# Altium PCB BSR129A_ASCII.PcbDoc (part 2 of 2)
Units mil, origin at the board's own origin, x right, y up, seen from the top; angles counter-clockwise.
Board outline 2165.87 x 2165.5 mil, 2 copper layers (Top Layer, Bottom Layer), stack 61.2 mil thick; 64 components, 16 nets, 93 pads, 184 vias.
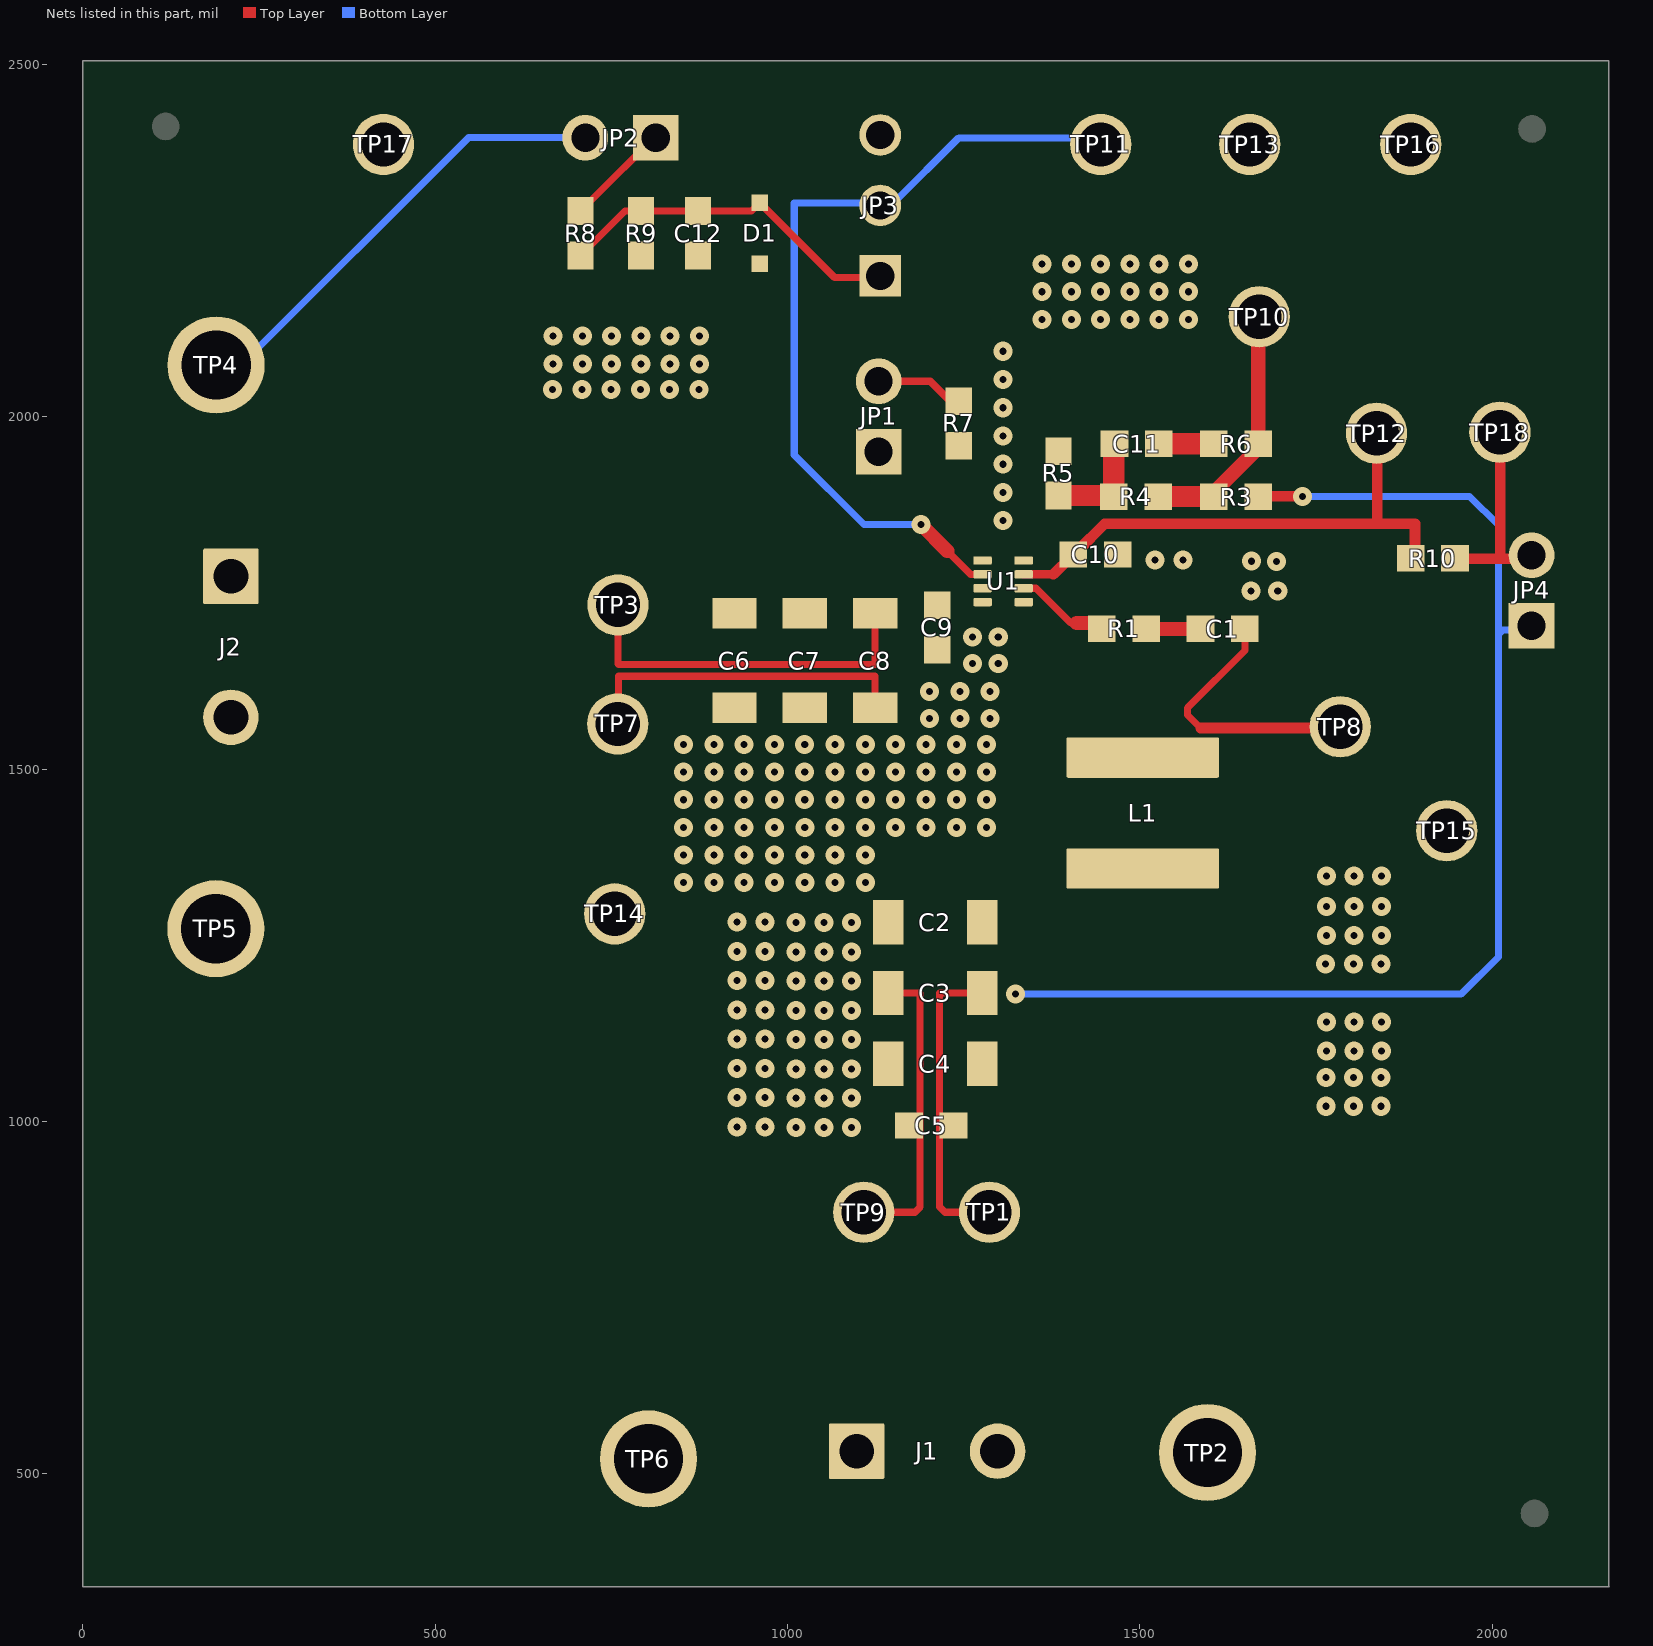
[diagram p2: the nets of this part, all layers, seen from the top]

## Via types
v1: diameter 27, hole 10, Top Layer to Bottom Layer, 184 vias

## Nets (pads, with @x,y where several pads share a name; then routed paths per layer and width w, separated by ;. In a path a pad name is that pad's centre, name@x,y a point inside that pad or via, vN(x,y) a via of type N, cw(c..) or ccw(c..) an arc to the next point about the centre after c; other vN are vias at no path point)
BST: R1.1 U1.6 | length 131.4
  Top Layer w10: U1.6@1335,1756.69 1352.81,1756.69 1402,1707.5 1410.5,1707.5
  Top Layer w20: 1410.5,1707.5 R1.1@1446,1707.5
EN: JP3.2 TP11.1 U1.2 | length 1173.2
  Top Layer w10: 1226.66,1809.66 1259.96,1776.37 U1.2@1276.73,1776.37
  Top Layer w20: v1(1189.33,1847) 1226.66,1809.66
  Bottom Layer w10: v1(1189.33,1847) 1108.3,1847 1009.5,1945.8 1009.5,2303.5 1131.5,2303.5 1132.5,2302.5 1149.5,2302.5 1243,2396 1435,2396 TP11.1@1444.5,2386.5
FB: C11.2 R4.1 R5.2 U1.8 | length 154.5
  Top Layer w30: R5.2@1384.48,1888.23 1461.49,1888.23 R4.1@1462.99,1886.73 1462.99,1960.74 C11.2@1463.98,1961.73
GND: C2.2 C3.2 C4.2 C5.2 C6.2 C7.2 C8.2 C9.2 C10.2 C12.2 D1.2 J1.1 J2.2 JP3.3 R5.1 R7.1 R9.1 TP5.1 TP6.1 TP7.1 TP9.1 TP13.1 TP14.1 TP15.1 TP16.1 TP17.1 U1.4 | length 964.9
  Top Layer w10: TP7.1@760,1529 760,1631.75 1124,1631.75 C8.2@1124,1587.54 ; C7.2@1024.5,1587.04 C7.2@1025,1587.54 ; TP9.1@1108,871 1180.88,871 1188.25,878.37 1188.25,1182.25 C3.2@1142.57,1182.25 ; C5.2@1169.69,991.35 C5.2@1172.5,994.16 C5.2@1187.91,994.16
  Bottom Layer w10: v1@1024.01,1535.35 v1(1024.36,1535) ; v1@1024.06,1417.6 v1(1024.41,1417.25)
  other v1: 1012,991.35 1051.5,991.35 1091,991.35 928.5,992.15 968,992.15 1764,1021.48 1803.25,1021.48 1842.5,1021.48 1012,1032.88 1051.5,1032.88 1091,1032.88 928.5,1033.69 968,1033.69 1764,1062.5 1803.25,1062.5 1842.5,1062.5 1012,1074.42 1051.5,1074.42 1091,1074.42 928.5,1075.23 968,1075.23 1764.75,1099.93 1804,1099.93 1843.25,1099.93 1012,1115.96 1051.5,1115.96 1091,1115.96 928.5,1116.77 968,1116.77 1764.75,1140.95 1804,1140.95 1843.25,1140.95 928.5,1158.31 968,1158.31 1012,1157.5 1051.5,1157.5 1091,1157.5 1012,1199.04 1051.5,1199.04 1091,1199.04 928.5,1199.85 968,1199.85 1763.75,1223.55 1803,1223.55 1842.25,1223.55 928.5,1241.39 968,1241.39 1012,1240.58 1051.5,1240.58 1091,1240.58 1764.75,1264.02 1804,1264.02 1843.25,1264.02 1012,1282.12 1051.5,1282.12 1091,1282.12 928.5,1282.93 968,1282.93 1764.75,1305.05 1804,1305.05 1843.25,1305.05 852.32,1338.75 895.34,1338.75 938.36,1338.75 981.39,1338.75 1024.41,1338.75 1067.43,1338.75 1110.45,1338.75 1764.75,1348.55 1804,1348.55 1843.25,1348.55 852.32,1378 895.34,1378 938.36,1378 981.39,1378 1024.41,1378 1067.43,1378 1110.45,1378 852.32,1417.25 895.34,1417.25 938.36,1417.25 981.39,1417.25 1067.43,1417.25 1110.45,1417.25 1153.48,1417.25 1196.5,1417.25 1239.52,1417.25 1282.55,1417.25 852.27,1456.5 895.3,1456.5 938.32,1456.5 981.34,1456.5 1024.36,1456.5 1067.39,1456.5 1110.41,1456.5 1153.43,1456.5 1196.45,1456.5 1239.48,1456.5 1282.5,1456.5 852.27,1495.75 895.3,1495.75 938.32,1495.75 981.34,1495.75 1024.36,1495.75 1067.39,1495.75 1110.41,1495.75 1153.43,1495.75 1196.45,1495.75 1239.48,1495.75 1282.5,1495.75 852.27,1535 895.3,1535 938.32,1535 981.34,1535 1067.39,1535 1110.41,1535 1153.43,1535 1196.45,1535 1239.48,1535 1282.5,1535 1201.45,1572 1244.48,1572 1287.5,1572 1201.45,1610.25 1244.48,1610.25 1287.5,1610.25 1262.48,1650 1299.02,1650 1262.48,1687.25 1299.02,1687.5 1695.72,1752.5 1657.5,1752.73 1694,1794.5 1658.5,1795 1561,1796.5 1521.48,1796.77 1305.5,1852.5 1305.5,1892.59 1305.5,1932.67 1305.5,1972.76 1305.5,2012.85 666.46,2039 708,2039 749.54,2039 791.08,2039 832.62,2039 874.15,2039 1305.5,2052.94 667.31,2074.95 708.85,2074.95 750.38,2074.95 791.92,2074.95 833.46,2074.95 875,2074.95 1305.5,2093.02 667.31,2114.45 708.85,2114.45 750.38,2114.45 791.92,2114.45 833.46,2114.45 875,2114.45 1361.31,2138 1402.85,2138 1444.38,2138 1485.92,2138 1527.46,2138 1569,2138 1361.31,2177.5 1402.85,2177.5 1444.38,2177.5 1485.92,2177.5 1527.46,2177.5 1569,2177.5 1361.31,2217 1402.85,2217 1444.38,2217 1485.92,2217 1527.46,2217 1569,2217
NetC1_2: C1.2 R1.2 | length 77
  Top Layer w20: R1.2@1508.99,1699 C1.2@1586,1699
NetC11_1: C11.1 R6.1 | length 78
  Top Layer w30: C11.1@1526.97,1961.73 R6.1@1604.99,1961.73
NetC12_1: C12.1 D1.1 JP3.1 R8.1 R9.2 | length 486.2
  Top Layer w10: R8.1@706.17,2228.95 769.16,2291.94 R9.2@792,2291.94 C12.1@872.9,2291.94 948.63,2291.94 D1.1@960.5,2303.81 1066.31,2198 JP3.1@1117.5,2198
NetJP1_2: JP1.2 R7.2 | length 135.2
  Top Layer w10: JP1.2@1120,2073.5 1143.02,2050.48 1202.51,2050.48 R7.2@1233,2019.99
NetJP2_1: JP2.1 R8.2 | length 172.3
  Top Layer w10: R8.2@706.17,2291.94 JP2.1@828,2413.77
NetJP4_2: JP4.2 R10.1 TP18.1 | length 254.2
  Top Layer w15: R10.1@1962.5,1798.5 2011.5,1798.5 ; TP18.1@2011.5,1955.98 2011.5,1798.5 ; JP4.2@2058,1801.5 2055,1798.5 2011.5,1798.5
NetR3_1: R3.1 R4.2 R6.2 TP10.1 | length 337.1
  Top Layer w10: R3.1@1604.98,1886.73 R3.1@1604.98,1892.98 ; R6.2@1667.98,1955.98 R6.2@1667.98,1961.73
  Top Layer w20: R3.1@1604.98,1892.98 R6.2@1667.98,1955.98 ; R6.2@1667.98,1961.73 1667.98,2117.98 TP10.1@1668.5,2118.5
  Top Layer w30: R4.2@1525.98,1886.73 R3.1@1604.98,1886.73
RT: JP1.1 U1.1
SS: C10.1 R10.2 TP12.1 U1.7 | length 738.8
  Top Layer w10: C10.1@1411.5,1801.13 C10.1@1412.13,1801.13 ; 1836,1848 1837,1849
  Top Layer w12: U1.7@1335,1776.37 1377.37,1776.37
  Top Layer w15: 1377.37,1776.37 C10.1@1402.5,1801.5 ; C10.1@1411.51,1809.5 1450.01,1848 1836,1848 1890.5,1848 1890.5,1807.51 R10.2@1893.39,1804.62 ; 1837,1849 TP12.1@1837,1955.98
  Top Layer w20: C10.1@1402.5,1801.5 1403.51,1801.5 C10.1@1411.51,1809.5
SW: C1.1 L1.1 TP8.1 U1.5 | length 404
  Top Layer w10: 1586.21,1558.31 1567.5,1577.02 1567.5,1587 1648.99,1668.49 C1.1@1648.99,1699
  Top Layer w15: 1586.21,1558.31 TP8.1@1808,1558.31
VIN: C6.1 C7.1 C8.1 C9.1 J2.1 JP2.2 TP3.1 TP4.1 U1.3 | length 1163.1
  Top Layer w10: TP3.1@759.33,1733 759.33,1649.23 759.81,1648.75 1124.25,1648.75 C8.1@1124.25,1705.13
  Bottom Layer w10: TP4.1@189,2073.5 224.5,2073.5 547.5,2396.5 JP2.2@713,2396.5
VOUT: C2.1 C3.1 C4.1 C5.1 J1.2 JP4.1 L1.2 R3.2 TP1.1 TP2.1 | length 2210.6
  Top Layer w10: C5.1@1235.5,994.16 1215.84,994.16 1215.5,994.5 ; C3.1@1276.43,1182.25 1215.5,1182.25 1215.5,994.5 ; TP1.1@1286.5,871 1223.34,871 1215.5,878.84 1215.5,994.5 ; R3.2@1667.97,1886.73 R3.2@1668.24,1887
  Top Layer w15: R3.2@1668.24,1887 v1(1731,1887)
  Bottom Layer w10: v1(1323.76,1180.5) 1956,1180.5 2008.79,1233.29 2008.79,1691 ; v1(1731,1887) 1968,1887 2008.79,1846.21 2008.79,1691 ; JP4.1@2080.5,1697.1 2014.89,1697.1 2008.79,1691
pads on no net: FID1.1 FID2.1 FID3.1 LBL1.0 SH-JP1.0 SH-JP2.0 SH-JP3.0 SH-JP4.0

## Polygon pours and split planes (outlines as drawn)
GND on Bottom Layer "Bottom Layer-GND" (solid, pour order 157): -102.5,2537.5 -102.5,292.5 2227.5,292.5 2227.5,2537.5
no net on Bottom Layer "BOTTOM_LAYER_NONET_P106" (solid, remove dead copper, pour order 106): -38.5,1953.5
GND on Top Layer "Top Layer-GND" (solid, pour order 153): -53.5,2550.5 2194.5,2550.5 2194.5,282 2176.5,264 -53.5,264
VOUT on Top Layer "Top Layer-VOUT" (solid, pour order 151): 1724,360 1719,355 1219.5,355 1215,359.5 1215,1390 1220,1395 1719,1395 1724,1390
no net on Top Layer "Top Layer-No Net" (solid, pour order 149): 1676.5,355
no net on Top Layer "Top Layer-No Net 1" (solid, pour order 147): 1205,365
no net on Top Layer "TOP_LAYER_NONET_P145" (solid, remove dead copper, pour order 145): 1632,1760.8
FB on Top Layer "TOP_LAYER_FB_P143" (solid, remove dead copper, pour order 143): 1322,1790.5 1348,1790.5 1348,1807 1403.18,1862.18 1403.18,1879 1376,1879 1322,1825
RT on Top Layer "TOP_LAYER_RT_P139" (solid, remove dead copper, pour order 139): 1289.5,1790.5 1264,1790.5 1264,1806.5 1152,1918.5 1095,1918.5 1095,1982.5 1160.5,1982.5 1160.5,1954 1289.5,1825
VIN on Top Layer "TOP_LAYER_VIN_P132" (solid, remove dead copper, pour order 132): 1259.12,1751 1290,1751 1290,1762.5 1263.63,1762.5 1235.13,1791 1209.5,1791 987.5,2013 597,2013 429.5,2180.5 381,2229 28.5,2229 28.5,1656.5 1144,1656.5 1190,1702.5 1233.15,1702.5
SW on Top Layer "TOP_LAYER_SW_P118" (solid, remove dead copper, pour order 118): 1322,1743 1322,1505 1337,1490 1625,1490 1640.5,1505.5 1640.5,1655 1635,1660.5 1429.5,1660.5 1347,1743
no net on Top Solder (solid): 1373.28,1490 1373.28,1599 1637,1599 1637,1490
no net on Top Solder (solid): 1373.5,1395.5 1636.41,1395.5 1636.41,1193.5 1373.5,1193.5
no net on Top Solder "NONET_L-01_P-001" (solid, remove dead copper): 1289.5,1790

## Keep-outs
Keep-Out Layer:
  text ".Layer_Name" at 570,-868.49 h60

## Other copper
Top Layer:
  text ".Layer_Name" at 570,-868.49 h60
Bottom Layer:
  text ".Layer_Name" at 570,-868.49 h60

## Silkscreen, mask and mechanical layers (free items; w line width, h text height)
Top Overlay:
  text "OFF" at 1197.79,2421 h30
  text "GND" at 514.5,2375 h30
  text "GND" at 1970,2261.5 h30
  text "GND" at 1716.5,2257.5 h30
  text "EN" at 1497.79,2255 h30
  text "ON" at 1197.79,2217.5 h30
  text "BODE" at 1757,2182.5 h30
  text "VIN" at 152,2178 h30
  text "S+" at 745,1866.5 h30
  text "SS/PG" at 1853.31,1864.31 h30
  text "SW" at 1837,1644.18 h30
  text "S-" at 744,1402 h30
  text "GND" at 143.53,1377 h30
  text "GND" at 1888,1238 h30
  text "GND" at 718.59,1121.5 h30
  text "S-" at 962.5,841.5 h30
  text "S+" at 1383.5,842.44 h30
  text "BSR129A" at 1740.5,639 h100
  text "VOUT" at 1749.5,514 h30
  text "GND" at 564.5,505 h30
  text ".Layer_Name" at 570,-868.49 h30
Bottom Overlay:
  text ".Layer_Name" at 570,-868.49 h60
Top Paste:
  text ".Layer_Name" at 570,-868.49 h60
Bottom Paste:
  text ".Layer_Name" at 570,-868.49 h60
Top Solder:
  text ".Layer_Name" at 570,-868.49 h60
  text ".Layer_Name" at 570,-868.49 h60
Bottom Solder:
  text ".Layer_Name" at 570,-868.49 h60
Drill Guide:
  text ".Layer_Name" at 570,-868.49 h60
M1 Board Outline:
  lines w10: 0,339.65 0,2505 2165.35,2505 2165.35,339.65 ; 0.52,339.5 2165.87,339.5
  text ".Layer_Name" at 570,-868.49 h60
M2 Board Dimensions:
  rectangle: 118,-410 493,-285
  rectangle: -7,-285 118,-160
  lines w7: -7,-285 993,-285 ; 118,-410 118,-160 ; 243,-410 243,-160 ; 493,-410 493,-160 ; 743,-410 743,-160 ; -7,-410 -7,-160 993,-160 993,-410 -7,-410
  text ".Layer_Name" at 570,-868.49 h60
M3 3D STEP Top:
  text ".Layer_Name" at 570,-868.49 h60
M4 3D STEP Bottom:
  text ".Layer_Name" at 570,-868.49 h60
M5 Assembly Top:
  lines w10: -299,-940.17 6301,-940.17 ; -299,-736.83 6303,-736.83 ; -299,-533.5 -299,-1143.5 3706,-1143.5 6303,-1143.5 6303,-533.5 -298.5,-533.5 -298.5,-1143.5 1277,-1143.5 ; 2166,-1143.5 2166,-533.5 ; 3433,-736.83 3433,-533.5 ; 4273,-736.83 4273,-533.5 ; 4895,-1150 4895,-947.17
  text "COMPONENTS MARKED 'DNP' SHOULD NOT BE POPULATED." at 1146.5,-328.5 h60
  text "ASSEMBLY VARIANT:" at 1146,-444 h60
  text ".VariantName" at 2182,-444 h60
  text "PCB VIEWED FROM TOP SIDE" at -235.5,-665.67 h60
  text "BOARD #:" at 2241,-665.67 h60
  text ".PRJ_Number" at 2786.5,-665.67 h60
  text "REV:" at 3631,-665.67 h60
  text ".PCB_Rev" at 3922.5,-665.67 h60
  text "SVN REV:" at 4469,-665.67 h60
  text ".VersionControl_RevNumber" at 4975,-665.67 h60
  text "TID #:" at 2241,-869 h60
  text ".TID" at 2786.5,-869 h60
  text "PLOT NAME =" at -235.5,-1074.34 h60
  text ".plot_File_Name" at 570,-1074.34 h60
  text "GENERATED    :" at 2243,-1074.34 h60
  text ".Print_Date" at 3112.5,-1074.34 h60
  text ".Print_Time" at 3841.5,-1074.34 h60
  text "TEXAS INSTRUMENTS" at 5106,-1074.34 h60
M6 Assembly Bottom:
  lines w10: -299.5,-737.33 6302.5,-737.33 ; -297.5,-940.67 6302.5,-940.67 ; 1108.5,-1150.5 1108.5,-947.67 ; 1730.5,-737.33 1730.5,-534 ; 2570.5,-737.33 2570.5,-534 ; 3837.5,-1144 3837.5,-534 ; 4726.5,-1144 6302,-1144 6302,-534 -299.5,-534 -299.5,-1144 2297.5,-1144 6302.5,-1144 6302.5,-534
  text "COMPONENTS MARKED 'DNP' SHOULD NOT BE POPULATED." at 6095,-328 h60
  text ".VariantName" at 5051,-444 h60
  text "ASSEMBLY VARIANT:" at 6090,-444 h60
  text ".VersionControl_RevNumber" at 1028.5,-666.17 h60
  text "SVN REV:" at 1534.5,-666.17 h60
  text ".PCB_Rev" at 2081,-666.17 h60
  text "REV:" at 2372.5,-666.17 h60
  text ".PRJ_Number" at 3217,-666.17 h60
  text "BOARD #:" at 3762.5,-666.17 h60
  text "PCB VIEWED FROM BOTTOM SIDE" at 6239,-666.17 h60
  text ".TID" at 3217,-869.5 h60
  text "TID #:" at 3762.5,-869.5 h60
  text "TEXAS INSTRUMENTS" at 897.5,-1074.84 h60
  text ".Print_Time" at 2162,-1074.84 h60
  text ".Print_Date" at 2891,-1074.84 h60
  text "GENERATED    :" at 3760.5,-1074.84 h60
  text ".plot_File_Name" at 5433.5,-1074.84 h60
  text "PLOT NAME =" at 6239,-1074.84 h60
M9 Title Sheet:
  lines w10: -498.5,1031.5 -298.5,1031.5 ; -498.5,3406.5 -298.5,3406.5 ; -498.5,5781.5 -298.5,5781.5 ; 2001.5,-1343.5 2001.5,-1143.5 ; 2001.5,7956.5 2001.5,8156.5 ; 4501.5,-1343.5 4501.5,-1143.5 ; 4501.5,7956.5 4501.5,8156.5 ; 6314,-1143.5 6314,-533.5 11296.5,-533.5 ; 7001.5,-1343.5 7001.5,-1143.5 ; 7001.5,7956.5 7001.5,8156.5 ; 9501.5,-1343.5 9501.5,-1143.5 ; 9501.5,7956.5 9501.5,8156.5 ; 11296.5,-1143.5 11296.5,-533.5 ; 11296.5,-833.5 14296.5,-833.5 ; 11296.5,-233.5 14296.5,-233.5 ; 11297.5,360.5 14297.5,360.5 ; 12001.5,-1343.5 12001.5,-1143.5 ; 12001.5,7956.5 12001.5,8156.5 ; 12801.5,-1133.5 12801.5,-533.5 ; 14296.5,-533.5 11296.5,-533.5 ; 14296.5,66.5 11296.5,66.5 ; 14301.5,56.5 14301.5,-1143.5 ; 14301.5,861 11297.5,861 11296.5,861 11296.5,360.5 11296.5,66.5 ; 14301.5,1031.5 14501.5,1031.5 ; 14301.5,3406.5 14501.5,3406.5 ; 14301.5,5781.5 14501.5,5781.5 ; 11296.5,-533.5 11296.5,66.5 ; 14301.5,-1143.5 -298.5,-1143.5 -298.5,7956.5 14301.5,7956.5 14301.5,-1143.5 ; -498.5,-1343.5 14501.5,-1343.5 14501.5,8156.5 -498.5,8156.5 -498.5,-1343.5
  text "1" at 732.84,8026.5 h70
  text "2" at 3228.5,8026.5 h70
  text "3" at 5717.84,8026.5 h70
  text "4" at 8224.51,8026.5 h70
  text "5" at 10723.5,8026.5 h70
  text "6" at 13228.5,8026.5 h70
  text "A" at -423.5,6883.5 h70
  text "A" at 14376.5,6883.5 h70
  text "B" at -423.5,4503.5 h70
  text "B" at 14376.5,4503.5 h70
  text "C" at -423.5,2128.5 h70
  text "C" at 14376.5,2128.5 h70
  text "PROJECT TITLE:" at 11336.5,267.5 h45
  text ".PRJ_Title" at 11386.5,134.17 h70
  text "DESIGNED FOR:" at 11336.5,-33.5 h45
  text ".PRJ_Customer" at 11386.5,-173.5 h70
  text "D" at -423.5,-241.5 h70
  text "D" at 14376.5,-241.5 h70
  text "FILE NAME:" at 11336.5,-333.5 h45
  text ".PCB_File_Name_No_Path" at 11386.5,-453.5 h70
  text "Texas Instruments (TI) and/or its licensors do not warrant the accuracy or completeness of this specification" at 6367,-615.34 h45
  text "ENGINEER:" at 11336.5,-623.5 h45
  text "LAYOUT BY:" at 12841.5,-623.5 h45
  text "or any information contained therein. TI and/or its licensors do not warrant that this design will meet" at 6322.01,-728 h45
  text "Ruby.Li" at 11386.5,-778.49 h70
  text "Ruby.Li" at 12892,-778.49 h70
  text "the specifications, will be suitable for your application or fit for any particular purpose, or will operate in" at 6322.01,-840.67 h45
  text ".Layer_Name" at 570,-868.49 h60
  text "ALTIUM DESIGNER VERSION:" at 12841.5,-933.5 h45
  text "an implementation. TI and/or its licensors do not warrant that the design is production worthy. You should" at 6322.01,-953.33 h45
  text "completely validate and test your design implementation to confirm the system functionality for your application." at 6367,-1066 h45
  text ".print_Scale" at 11386.5,-1066.83 h70
  text ".Application_BuildNumber" at 12892,-1066.83 h70
  text "1" at 732.84,-1273.5 h70
  text "2" at 3228.5,-1273.5 h70
  text "3" at 5717.84,-1273.5 h70
  text "4" at 8224.51,-1273.5 h70
  text "5" at 10723.5,-1273.5 h70
  text "6" at 13228.5,-1273.5 h70
M10 Fab Notes:
  drawing of 173 lines, arcs and shapes, not listed
  text "DESIGN INFORMATION" at 12371.02,6191 h60
  text "MIN. TRACK WIDTH:" at 11726.46,6011 h60
  text "8" at 12822.7,6011 h60
  text "MIL" at 12977.46,6011 h60
  text "MIN. CLEARANCE:" at 11726.46,5879 h60
  text "0.2" at 12762.7,5879 h60
  text "mm" at 12977.46,5879 h60
  text "MIN. VIA PAD SIZE:" at 11726.46,5747 h60
  text "24" at 12792.71,5747 h60
  text "MIL" at 12977.46,5747 h60
  text "0.05mm (2MIL)" at 12421.46,5605.29 h60
  text "MINIMUM ANNULAR RING" at 11397.23,5601 h60
  text "EXTERNAL" at 13129.46,5601 h60
  text "PER" at 11597.23,5483 h60
  text "IPC-D-275 CLASS 2 LEVEL C" at 11817.23,5483 h60
  text "MIL, HOLES" at 13305.46,5370.71 h60
  text "+/-" at 12913,5370 h60
  text "+/-" at 13767,5370 h60
  text "REGISTRATION TOLERANCES:" at 11397.23,5365 h60
  text "METAL" at 12597,5365 h60
  text "5" at 13173.2,5365 h60
  text "3" at 14006.2,5365 h60
  text "MIL" at 14122.46,5365 h60
  text "+/-" at 13767,5252 h60
  text "HOLE SIZE TOLERANCE (UNLESS OTHERWISE SPECIFIED):" at 11397.23,5247 h60
  text "3" at 14006.2,5247 h60
  text "MIL" at 14122.46,5247 h60
  text "MATERIAL:" at 11322.46,5037.54 h60
  text "FR-4 High Tg" at 12308.9,4897.21 h60
  text "FR-408" at 11743.46,4888.64 h60
  text "OTHER" at 13231.46,4888.64 h60
  text "X" at 12154,4885 h60
  text "62 MIL (1.6mm) +/-10%" at 12063.56,4725.92 h60
  text "THICKNESS:" at 11397.23,4721.64 h60
  text "X" at 11935.4,4721.64 h60
  text "OTHER" at 13348.46,4721.64 h60
  text "TOLERANCE:" at 11397.23,4563.64 h60
  text "X" at 12236.53,4563.64 h60
  text "ANSI IPC-6012 TYPE 3 CLASS 2" at 12423.48,4563.64 h60
  text "OTHER +/-" at 12423.46,4407.64 h60
  text "BOW & TWIST:" at 11397.23,4250.64 h60
  text "X" at 12236.53,4250.64 h60
  text "ANSI IPC-6012 TYPE 3 CLASS 2" at 12423.48,4250.64 h60
  text "OTHER +/-" at 12423.46,4092.13 h60
  text "DRILLING:" at 11322.46,3953.64 h60
  text "REFERENCE:" at 11397.23,3836.64 h60
  text "X" at 12045.46,3836.64 h60
  text "AS SHOWN" at 12232.46,3836.64 h60
  text "X" at 12946.46,3836.64 h60
  text "NC_DRILL FILES" at 13083.46,3836.64 h60
  text "PTH COPPER THICKNESS:" at 11397.23,3678.64 h60
  text "X" at 12527.46,3678.64 h60
  text "20-30 um" at 12664.46,3678.64 h60
  text "OTHER" at 13381.46,3678.64 h60
  text "BOARD FINISH:" at 11322.46,3519.64 h60
  text "SILKSCREEN:" at 11477.68,3401.64 h60
  text "X" at 12426.46,3401.64 h60
  text "TOP" at 12552.46,3401.64 h60
  text "X" at 12936.46,3401.64 h60
  text "BOTTOM" at 13063.46,3401.64 h60
  text "SILKSCREEN COLOR:" at 11477.68,3234.64 h60
  text "X" at 12425.42,3234.64 h60
  text "WHITE" at 12552.46,3234.64 h60
  text "OTHER" at 13063.46,3234.64 h60
  text "X" at 12556.42,3075.44 h60
  text "GREEN" at 12683.46,3075.44 h60
  text "OTHER" at 13301.46,3075.44 h60
  text "SOLDER RESIST COLOR:" at 11477.68,3064.64 h60
  text "X" at 12556.42,2905.44 h60
  text "MATTE" at 12683.46,2905.44 h60
  text "SEMI-GLOSS" at 13301,2904.8 h60
  text "IMMERSION GOLD (ENIG)" at 12383.46,2716.92 h60
  text "ENEPIG" at 13721,2713.64 h60
  text "SURFACE FINISH:" at 11322.46,2712.64 h60
  text "X" at 12196.51,2712.64 h60
  text "IMM. TIN/SILVER OR EQUIV" at 11652,2555.64 h60
  text "OTHER" at 13083.46,2555.64 h60
  text "ARRAY/PANEL:" at 11322.46,2376.64 h60
  text "CUT AND TRIM PER M1 BOARD OUTLINE" at 12383.46,2372.35 h60
  text "N.C. ROUTE" at 12383.46,2220.64 h60
  text "X" at 13062.46,2220.64 h60
  text "V. SCORE" at 13249.46,2220.64 h60
  text "CERTIFICATION:" at 11322.46,2083.64 h60
  text "MATERIALS AND WORKMANSHIP FOR ALL PCBS" at 12047.46,2083.64 h60
  text "TO MEET OR EXCEED THE REQUIREMENTS OF:" at 12047.46,1985.64 h60
  text "X" at 11673.96,1849.13 h60
  text "ANSI IPC-A-600F CLASS ->" at 11812.96,1849.13 h60
  text "X" at 13452.02,1849.13 h60
  text "2" at 13570.96,1849.14 h60
  text "1" at 13255.96,1847.64 h60
  text "3" at 13924.96,1847.64 h60
  text "X" at 12488.02,1689.64 h60
  text "RoHS" at 12624.96,1689.64 h60
  text "OTHER" at 13269.36,1689.64 h60
  text "PER ORDER" at 13666.42,1689.64 h60
  text "ALL BOARDS MUST MEET OR EXCEED UL94-V0 REQUIREMENTS." at 11350,1524 h60
  text "PCB MUST BEAR THE UL94V-0 UL REGISTERED MATERIAL ID NUMBER" at 11350,1404 h60
  text "ADDITIONAL REQUIREMENTS:" at 11322.46,1230.64 h60
  text "MICROSECTION:" at 11397.23,1115.64 h60
  text "YES" at 12302.96,1115.64 h60
  text "REQUIRED" at 13164.46,959.49 h60
  text "BARE BOARD ELEC. TEST:" at 11397.23,956.64 h60
  text "NONE" at 12702.96,956.64 h60
  text "X" at 13037.46,956.64 h60
  text "PER ORDER" at 13756.46,956.64 h60
  text ".Layer_Name" at 570,-868.49 h60
M11 Gerber Information:
  lines w10: -299,-940.17 6301,-940.17 ; -299,-736.83 6303,-736.83 ; -299,-533.5 -299,-1143.5 3706,-1143.5 6303,-1143.5 6303,-533.5 -298.5,-533.5 -298.5,-1143.5 1277,-1143.5 ; 2166,-1143.5 2166,-533.5 ; 3433,-736.83 3433,-533.5 ; 4273,-736.83 4273,-533.5 ; 4895,-1150 4895,-947.17
  text "ALL ARTWORK VIEWED FROM TOP SIDE" at -235.5,-665.67 h60
  text "BOARD #:" at 2241,-665.67 h60
  text ".PRJ_Number" at 2786.5,-665.67 h60
  text "REV:" at 3631,-665.67 h60
  text ".PCB_Rev" at 3922.5,-665.67 h60
  text "SVN REV:" at 4469,-665.67 h60
  text ".VersionControl_RevNumber" at 4975,-665.67 h60
  text "LAYER NAME =" at -235.5,-868.49 h60
  text "TID #:" at 2241,-869 h60
  text ".TID" at 2786.5,-869 h60
  text "PLOT NAME =" at -235.5,-1074.34 h60
  text ".plot_File_Name" at 570,-1074.34 h60
  text "GENERATED    :" at 2243,-1074.34 h60
  text ".Print_Date" at 3112.5,-1074.34 h60
  text ".Print_Time" at 3841.5,-1074.34 h60
  text "TEXAS INSTRUMENTS" at 5106,-1074.34 h60
M12 Stackup:
  lines w1: 5869.1,2504.94 5946.66,2582.5 6066.66,2702.5 6186.66,2822.5 6306.66,2942.5 6426.66,3062.5 ; 5869.1,2564.94 5886.66,2582.5 6006.66,2702.5 6126.66,2822.5 6246.66,2942.5 6366.66,3062.5 6426.66,3122.5 ; 5869.1,2624.94 5946.66,2702.5 6066.66,2822.5 6186.66,2942.5 6306.66,3062.5 6426.66,3182.5 ; 5869.1,2684.94 5886.66,2702.5 6006.66,2822.5 6126.66,2942.5 6246.66,3062.5 6366.66,3182.5 ; 5869.1,2744.94 5946.66,2822.5 6066.66,2942.5 6186.66,3062.5 6306.66,3182.5 ; 5869.1,2804.94 5886.66,2822.5 6006.66,2942.5 6126.66,3062.5 6246.66,3182.5 ; 5869.1,2864.94 5946.66,2942.5 6066.66,3062.5 6186.66,3182.5 ; 5869.1,2924.94 5886.66,2942.5 6006.66,3062.5 6126.66,3182.5 ; 5869.1,2984.94 5946.66,3062.5 6066.66,3182.5 ; 5869.1,3044.94 5886.66,3062.5 6006.66,3182.5 ; 5869.1,3104.94 5946.66,3182.5 ; 5869.1,3164.94 5886.66,3182.5 ; 5886.66,2462.5 6006.66,2582.5 6126.66,2702.5 6246.66,2822.5 6366.66,2942.5 6426.66,3002.5 ; 5946.66,2462.5 6066.66,2582.5 6186.66,2702.5 6306.66,2822.5 6426.66,2942.5 ; 6006.66,2462.5 6126.66,2582.5 6246.66,2702.5 6366.66,2822.5 6426.66,2882.5 ; 6066.66,2462.5 6186.66,2582.5 6306.66,2702.5 6426.66,2822.5 ; 6126.66,2462.5 6246.66,2582.5 6366.66,2702.5 6426.66,2762.5 ; 6186.66,2462.5 6306.66,2582.5 6426.66,2702.5 ; 6246.66,2462.5 6366.66,2582.5 6426.66,2642.5 ; 6306.66,2462.5 6426.66,2582.5 ; 6366.66,2462.5 6426.66,2522.5
  lines w15: 4034.5,2582.5 4285.59,2582.5 4742.59,2582.5 5178.94,2582.5 5537.36,2582.5 5869.1,2582.5 6426.66,2582.5 ; 4034.5,2702.5 4285.59,2702.5 4742.59,2702.5 5178.94,2702.5 5537.36,2702.5 5869.1,2702.5 6426.66,2702.5 ; 4034.5,2822.5 4285.59,2822.5 4742.59,2822.5 5178.94,2822.5 5537.36,2822.5 5869.1,2822.5 6426.66,2822.5 ; 4034.5,2942.5 4285.59,2942.5 4742.59,2942.5 5178.94,2942.5 5537.36,2942.5 5869.1,2942.5 6426.66,2942.5 ; 4034.5,3062.5 4285.59,3062.5 4742.59,3062.5 5178.94,3062.5 5537.36,3062.5 5869.1,3062.5 6426.66,3062.5 ; 4034.5,3182.5 6426.66,3182.5 ; 4285.59,3302.5 4285.59,2462.5 ; 4742.59,3302.5 4742.59,2462.5 ; 5178.94,3302.5 5178.94,2462.5 ; 5537.36,3302.5 5537.36,2462.5 ; 5869.1,3302.5 5869.1,2462.5 ; 4285.59,2462.5 4034.5,2462.5 4034.5,3302.5 6426.66,3302.5 6426.66,2462.5 5869.1,2462.5 ; 4285.59,2462.5 4742.59,2462.5 ; 4742.59,2462.5 5178.94,2462.5 ; 5178.94,2462.5 5537.36,2462.5 ; 5537.36,2462.5 5869.1,2462.5
  text "Layer" at 4094.5,3212.5 h60
  text "Name" at 4345.59,3212.5 h60
  text "Material" at 4802.59,3212.5 h60
  text "Thickness" at 5238.94,3212.5 h60
  text "Constant" at 5597.36,3212.5 h60
  text "Board Layer Stack" at 5929.1,3212.5 h60
  text "1" at 4094.5,3092.5 h60
  text "Top Overlay" at 4345.59,3092.5 h60
  text "2" at 4094.5,2972.5 h60
  text "Top Solder" at 4345.59,2972.5 h60
  text "Solder Resist" at 4802.59,2972.5 h60
  text "0.40mil" at 5238.94,2972.5 h60
  text "3.5" at 5597.36,2972.5 h60
  text "3" at 4094.5,2852.5 h60
  text "Top Layer" at 4345.59,2852.5 h60
  text "Copper" at 4802.59,2852.5 h60
  text "2.80mil" at 5238.94,2852.5 h60
  text "4" at 4094.5,2732.5 h60
  text "Dielectric1" at 4345.59,2732.5 h60
  text "FR-4 High Tg" at 4802.59,2732.5 h60
  text "55.60mil" at 5238.94,2732.5 h60
  text "4.8" at 5597.36,2732.5 h60
  text "5" at 4094.5,2612.5 h60
  text "Bottom Layer" at 4345.59,2612.5 h60
  text "Copper" at 4802.59,2612.5 h60
  text "2.80mil" at 5238.94,2612.5 h60
  text "6" at 4094.5,2492.5 h60
  text "Bottom Solder" at 4345.59,2492.5 h60
  text "Solder Resist" at 4802.59,2492.5 h60
  text "0.40mil" at 5238.94,2492.5 h60
  text "3.5" at 5597.36,2492.5 h60
  text ".Layer_Name" at 570,-868.49 h60
M13 Component Bodies Top:
  text ".Layer_Name" at 570,-868.49 h60
M14 Component Bodies Bottom:
  text ".Layer_Name" at 570,-868.49 h60
M15 Courtyards Top:
  text ".Layer_Name" at 570,-868.49 h60
M16 Courtyards Bottom:
  text ".Layer_Name" at 570,-868.49 h60
Drill Drawing:
  lines w10: 4081.59,1558.88 4136.84,1558.88 4136.84,1614.13 4081.59,1614.13 4081.59,1558.88 ; 4081.59,1697.01 4095.4,1697.01 4109.22,1683.2 4123.03,1697.01 4136.84,1697.01 4123.03,1710.82 4136.84,1724.64 4123.03,1724.64 4109.22,1738.45 4095.4,1724.64 4081.59,1724.64 4095.4,1710.82 4081.59,1697.01 ; 4081.59,1807.52 4109.22,1821.33 4136.84,1807.52 4123.03,1835.14 4136.84,1862.77 4109.22,1848.96 4081.59,1862.77 4095.4,1835.14 4081.59,1807.52 ; 4081.59,1987.09 4136.84,1987.09 4109.22,1931.84 4081.59,1987.09 ; 4081.59,2083.78 4109.22,2056.16 4136.84,2083.78 4109.22,2111.41 4081.59,2083.78
  lines w12: 4031.5,1521.58 7262.99,1521.58 ; 4031.5,2143.18 7262.99,2143.18 ; 4369.36,1397.26 4369.36,2267.5 ; 4701.36,1397.26 4701.36,2267.5 ; 5337.93,1397.26 5337.93,2267.5 ; 5597.07,1397.26 5597.07,2267.5 ; 5972.22,1397.26 5972.22,2267.5 ; 6696.55,1397.26 6696.55,2267.5 ; 4031.5,1397.26 7262.99,1397.26 7262.99,2267.5 4031.5,2267.5 4031.5,1397.26
  text "Symbol" at 4106.09,2180.48 h72
  text "Quantity" at 4406.66,2180.48 h72
  text "Finished Hole Size" at 4738.66,2180.48 h72
  text "Plated" at 5375.22,2180.48 h72
  text "Hole Type" at 5634.36,2180.48 h72
  text "Drill Layer Pair" at 6009.52,2180.48 h72
  text "Hole Tolerance" at 6733.85,2180.48 h72
  text "184" at 4406.66,2056.16 h60
  text "10.00mil (0.254mm)" at 4738.66,2056.16 h60
  text "PTH" at 5375.22,2056.16 h60
  text "Round" at 5634.36,2056.16 h60
  text "Top Layer - Bottom Layer" at 6009.52,2056.16 h60
  text "9" at 4406.66,1931.84 h60
  text "40.00mil (1.016mm)" at 4738.66,1931.84 h60
  text "PTH" at 5375.22,1931.84 h60
  text "Round" at 5634.36,1931.84 h60
  text "Top Layer - Bottom Layer" at 6009.52,1931.84 h60
  text "4" at 4406.66,1807.52 h60
  text "49.21mil (1.250mm)" at 4738.66,1807.52 h60
  text "PTH" at 5375.22,1807.52 h60
  text "Round" at 5634.36,1807.52 h60
  text "Top Layer - Bottom Layer" at 6009.52,1807.52 h60
  text "14" at 4406.66,1683.2 h60
  text "63.00mil (1.600mm)" at 4738.66,1683.2 h60
  text "PTH" at 5375.22,1683.2 h60
  text "Round" at 5634.36,1683.2 h60
  text "Top Layer - Bottom Layer" at 6009.52,1683.2 h60
  text "4" at 4406.66,1558.88 h60
  text "98.43mil (2.500mm)" at 4738.66,1558.88 h60
  text "PTH" at 5375.22,1558.88 h60
  text "Round" at 5634.36,1558.88 h60
  text "Top Layer - Bottom Layer" at 6009.52,1558.88 h60
  text "215 Total" at 4406.66,1434.56 h60
  text ".Layer_Name" at 570,-868.49 h60
M17 Embedded Cavity:
  text ".Layer_Name" at 570,-868.49 h60
M18 Embedded Assembly:
  text ".Layer_Name" at 570,-868.49 h60
M19 Embedded Keepout:
  text ".Layer_Name" at 570,-868.49 h60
